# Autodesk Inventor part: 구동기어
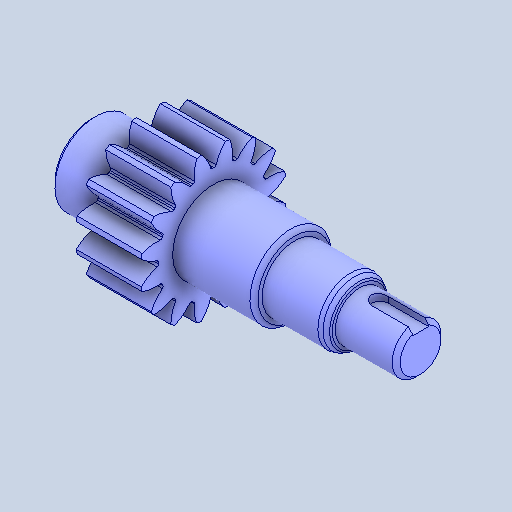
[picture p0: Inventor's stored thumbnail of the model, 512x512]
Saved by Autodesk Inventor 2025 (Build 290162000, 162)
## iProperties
Created: 2026-08
Part Number: 구동기어
Material: 일반
Document SubType Name: Modeling
Designer: KDI
Density: 1 g/cm^3
Appearance: 기본값
Author: jhkim
Sending System: Autodesk Inventor 2027
Preprocessor: ST-DEVELOPER v20.1
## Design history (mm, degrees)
feature "솔리드1"
node "솔리드2"
